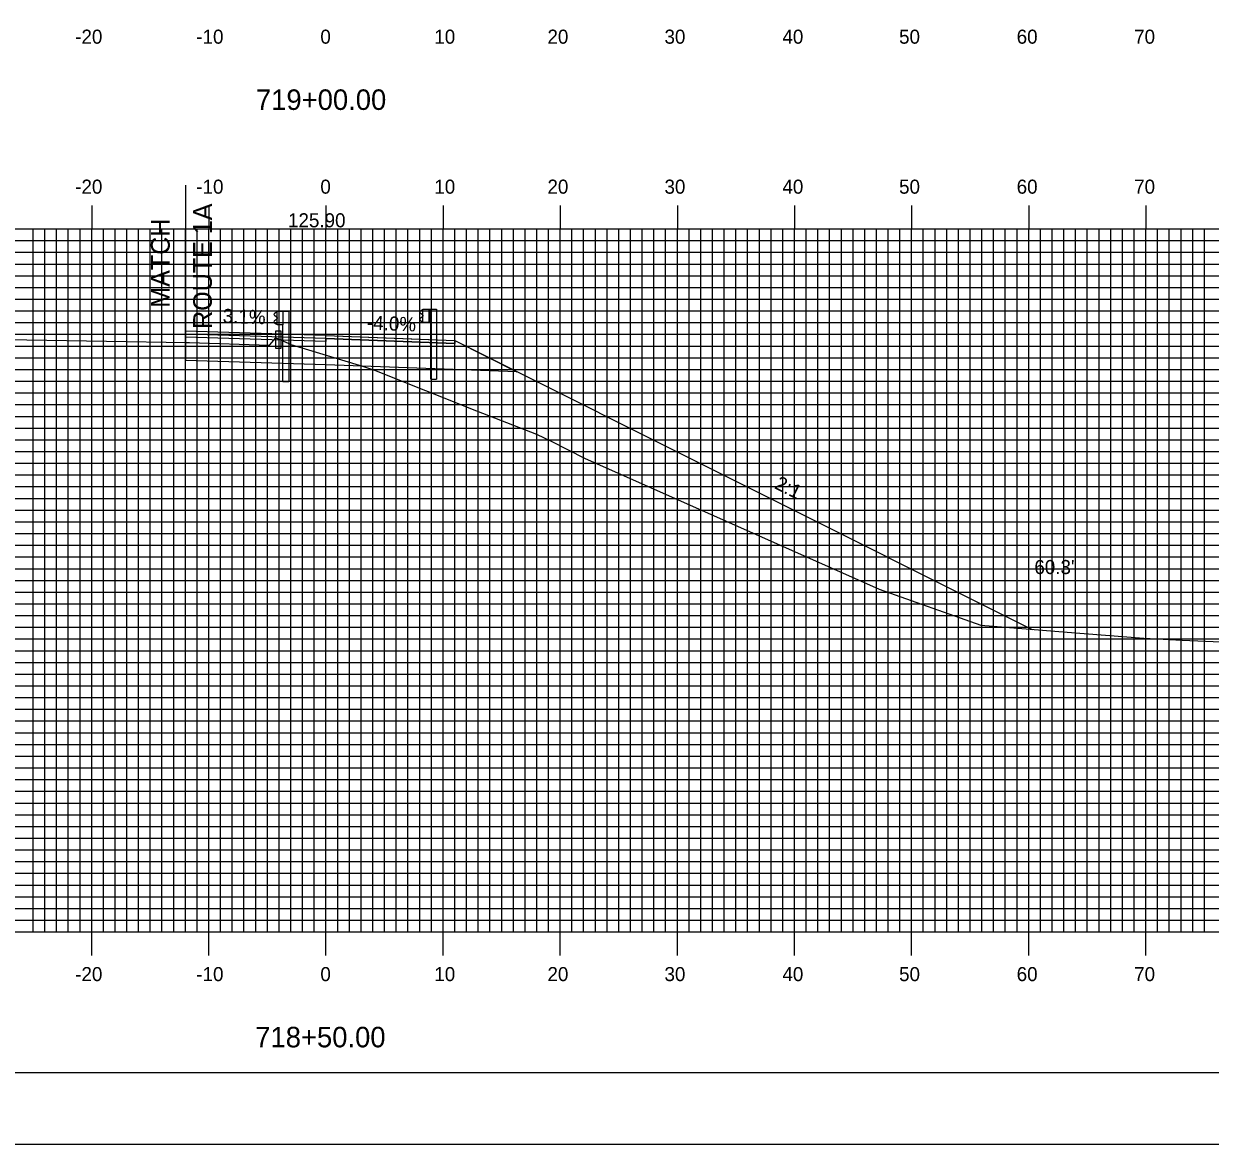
# Model space of a CAD drawing. Extents: x 857658 to 858001, y 364366 to 364586.
# Drawn here: x 857798 to 857899.3, y 364365.7 to 364461.3 of the extents above; entities that cross this region are included whole.
import ezdxf

# ---------------------------------------------------------------- set-up
doc = ezdxf.new("R2010")
doc.units = 0
for name, color, linetype in [('ANNOTATION', 7, 'Continuous'), ('BORDER', 7, 'Continuous'), ('D_Guardrail_Beam_Lt', 7, 'Continuous'), ('D_Roadway_Centerline', 7, 'Continuous'), ('D_Roadway_Centerline_Text', 7, 'Continuous'), ('D_Roadway_Edge_Shoulder', 7, 'Continuous'), ('D_Roadway_Edge_TW', 7, 'Continuous'), ('D_Roadway_Pavement', 7, 'Continuous'), ('D_Roadway_SlopeLines', 7, 'Continuous'), ('D_Roadway_SubGrade', 7, 'Continuous'), ('D_Text_Standard', 7, 'Continuous'), ('H_V ANNOTATION', 7, 'Continuous'), ('MAJOR', 7, 'Continuous'), ('MINOR', 7, 'Continuous'), ('PLOT BOUNDARY', 7, 'Continuous'), ('S_Curb_Type_1', 7, 'Continuous'), ('S_Guardrail_Beam', 7, 'Continuous'), ('S_Roadway_Centerline', 7, 'Continuous')]:
    doc.layers.add(name, color=color, linetype=linetype)

msp = doc.modelspace()

# ---------------------------------------------------------------- linework, layer by layer
at = {"layer": 'BORDER'}
msp.add_lwpolyline([(857674.25, 364371.79), (857994.25, 364371.79), (857994.25, 364581.79), (857674.25, 364581.79)], close=True, dxfattribs=at)
at = {"layer": 'D_Guardrail_Beam_Lt'}
for p, q in [((857832.03, 364436.85), (857831.89, 364436.75)), ((857831.89, 364436.61), (857832.08, 364436.47)), ((857832.08, 364436.27), (857831.89, 364436.14)), ((857832.12, 364436.87), (857832.05, 364436.86)), ((857832.11, 364436.41), (857832.11, 364436.34)), ((857832.12, 364436.95), (857832.81, 364436.95)), ((857832.12, 364435.79), (857832.12, 364436.95)), ((857832.64, 364436.95), (857832.64, 364435.79)), ((857832.74, 364436.95), (857832.74, 364435.79)), ((857832.81, 364436.95), (857833.28, 364436.95)), ((857832.81, 364436.95), (857832.81, 364435.79)), ((857833.28, 364436.95), (857833.28, 364430.95)), ((857831.89, 364435.99), (857832.03, 364435.89)), ((857832.05, 364435.89), (857832.12, 364435.87)), ((857832.81, 364435.79), (857832.12, 364435.79)), ((857832.79, 364430.95), (857832.79, 364435.79)), ((857832.79, 364430.95), (857833.28, 364430.95))]:
    msp.add_line(p, q, dxfattribs=at)
for centre, major_axis, start_param, end_param in [((857831.94, 364436.68), (-0.0877, 0), 5.323254, 7.243116), ((857832.05, 364436.82), (-0.0417, 0), 4.907132, 5.323254), ((857832.04, 364436.41), (0.0789, 0), 0, 0.959931), ((857832.04, 364436.34), (0.0789, 0), 5.323254, 6.283185), ((857831.94, 364436.06), (-0.0877, 0), 5.323254, 7.243116), ((857832.05, 364435.93), (-0.0417, 0), 0.959931, 1.376053)]:
    msp.add_ellipse(centre, major_axis=major_axis, ratio=0.995501, start_param=start_param, end_param=end_param, dxfattribs=at)
at = {"layer": 'D_Roadway_Centerline'}
for p, q in [((857823.85, 364434.69), (857811.85, 364435.06)), ((857823.85, 364434.44), (857811.85, 364434.81)), ((857823.85, 364434.19), (857811.85, 364434.56)), ((857823.85, 364432.19), (857811.85, 364432.56))]:
    msp.add_line(p, q, dxfattribs=at)
at = {"layer": 'D_Roadway_Edge_Shoulder'}
for points in [[(857823.85, 364434.69), (857834.85, 364434.25), (857834.85, 364434), (857823.85, 364434.44)], [(857823.85, 364434.69), (857831.85, 364434.37), (857831.85, 364434.37), (857834.85, 364434.25), (857834.85, 364434), (857823.85, 364434.44)]]:
    msp.add_lwpolyline(points, close=True, dxfattribs=at)
at = {"layer": 'D_Roadway_Edge_TW'}
msp.add_line((857811.85, 364435.12), (857811.85, 364434.87), dxfattribs=at)
at = {"layer": 'D_Roadway_Pavement'}
msp.add_line((857811.85, 364434.87), (857811.85, 364434.62), dxfattribs=at)
msp.add_lwpolyline([(857823.85, 364434.44), (857823.85, 364434.19)], dxfattribs=at)
msp.add_lwpolyline([(857823.85, 364434.44), (857823.85, 364434.19)], dxfattribs=at)
msp.add_lwpolyline([(857823.85, 364434.44), (857823.85, 364434.19)], dxfattribs=at)
msp.add_lwpolyline([(857823.85, 364434.44), (857823.85, 364434.19)], dxfattribs=at)
at = {"layer": 'D_Roadway_SlopeLines'}
msp.add_lwpolyline([(857834.85, 364434.25), (857884.13, 364409.61)], dxfattribs=at)
at = {"layer": 'D_Roadway_SubGrade'}
for p, q in [((857811.85, 364447.52), (857811.85, 364432.56)), ((857811.85, 364434.62), (857811.85, 364432.62))]:
    msp.add_line(p, q, dxfattribs=at)
msp.add_lwpolyline([(857823.85, 364434.19), (857823.85, 364434.44), (857834.85, 364434), (857834.85, 364434.25), (857840.14, 364431.6), (857823.85, 364432.19)], close=True, dxfattribs=at)
at = {"layer": 'MAJOR'}
for p, q in [((857803.85, 364445.79), (857803.85, 364443.79)), ((857813.85, 364445.79), (857813.85, 364443.79)), ((857823.85, 364445.79), (857823.85, 364443.79)), ((857833.85, 364445.79), (857833.85, 364443.79)), ((857843.85, 364445.79), (857843.85, 364443.79)), ((857853.85, 364445.79), (857853.85, 364443.79)), ((857863.85, 364445.79), (857863.85, 364443.79)), ((857873.85, 364445.79), (857873.85, 364443.79)), ((857883.85, 364445.79), (857883.85, 364443.79)), ((857893.85, 364445.79), (857893.85, 364443.79)), ((857683.85, 364443.79), (857963.85, 364443.79)), ((857683.85, 364443.79), (857963.85, 364443.79)), ((857803.85, 364383.79), (857803.85, 364443.79)), ((857813.85, 364383.79), (857813.85, 364443.79)), ((857823.85, 364383.79), (857823.85, 364443.79)), ((857833.85, 364383.79), (857833.85, 364443.79)), ((857843.85, 364383.79), (857843.85, 364443.79)), ((857853.85, 364383.79), (857853.85, 364443.79)), ((857863.85, 364383.79), (857863.85, 364443.79)), ((857873.85, 364383.79), (857873.85, 364443.79)), ((857883.85, 364383.79), (857883.85, 364443.79)), ((857893.85, 364383.79), (857893.85, 364443.79)), ((857683.85, 364438.79), (857963.85, 364438.79)), ((857683.85, 364433.79), (857963.85, 364433.79)), ((857683.85, 364428.79), (857963.85, 364428.79)), ((857683.85, 364423.79), (857963.85, 364423.79)), ((857683.85, 364418.79), (857963.85, 364418.79)), ((857683.85, 364413.79), (857963.85, 364413.79)), ((857683.85, 364408.79), (857963.85, 364408.79)), ((857683.85, 364403.79), (857963.85, 364403.79)), ((857683.85, 364398.79), (857963.85, 364398.79)), ((857683.85, 364393.79), (857963.85, 364393.79)), ((857683.85, 364388.79), (857963.85, 364388.79)), ((857683.85, 364383.79), (857963.85, 364383.79)), ((857683.85, 364383.79), (857963.85, 364383.79)), ((857803.85, 364381.78), (857803.85, 364383.79)), ((857813.85, 364381.78), (857813.85, 364383.79)), ((857823.85, 364381.78), (857823.85, 364383.79)), ((857833.85, 364381.78), (857833.85, 364383.79)), ((857843.85, 364381.78), (857843.85, 364383.79)), ((857853.85, 364381.78), (857853.85, 364383.79)), ((857863.85, 364381.78), (857863.85, 364383.79)), ((857873.85, 364381.78), (857873.85, 364383.79)), ((857883.85, 364381.78), (857883.85, 364383.79)), ((857893.85, 364381.78), (857893.85, 364383.79))]:
    msp.add_line(p, q, dxfattribs=at)
at = {"layer": 'MINOR'}
for p, q in [((857798.85, 364383.79), (857798.85, 364443.79)), ((857799.85, 364383.79), (857799.85, 364443.79)), ((857800.85, 364383.79), (857800.85, 364443.79)), ((857801.85, 364383.79), (857801.85, 364443.79)), ((857802.85, 364383.79), (857802.85, 364443.79)), ((857804.85, 364383.79), (857804.85, 364443.79)), ((857805.85, 364383.79), (857805.85, 364443.79)), ((857806.85, 364383.79), (857806.85, 364443.79)), ((857807.85, 364383.79), (857807.85, 364443.79)), ((857808.85, 364383.79), (857808.85, 364443.79)), ((857809.85, 364383.79), (857809.85, 364443.79)), ((857810.85, 364383.79), (857810.85, 364443.79)), ((857811.85, 364383.79), (857811.85, 364443.79)), ((857812.85, 364383.79), (857812.85, 364443.79)), ((857814.85, 364383.79), (857814.85, 364443.79)), ((857815.85, 364383.79), (857815.85, 364443.79)), ((857816.85, 364383.79), (857816.85, 364443.79)), ((857817.85, 364383.79), (857817.85, 364443.79)), ((857818.85, 364383.79), (857818.85, 364443.79)), ((857819.85, 364383.79), (857819.85, 364443.79)), ((857820.85, 364383.79), (857820.85, 364443.79)), ((857821.85, 364383.79), (857821.85, 364443.79)), ((857822.85, 364383.79), (857822.85, 364443.79)), ((857824.85, 364383.79), (857824.85, 364443.79)), ((857825.85, 364383.79), (857825.85, 364443.79)), ((857826.85, 364383.79), (857826.85, 364443.79)), ((857827.85, 364383.79), (857827.85, 364443.79)), ((857828.85, 364383.79), (857828.85, 364443.79)), ((857829.85, 364383.79), (857829.85, 364443.79)), ((857830.85, 364383.79), (857830.85, 364443.79)), ((857831.85, 364383.79), (857831.85, 364443.79)), ((857832.85, 364383.79), (857832.85, 364443.79)), ((857834.85, 364383.79), (857834.85, 364443.79)), ((857835.85, 364383.79), (857835.85, 364443.79)), ((857836.85, 364383.79), (857836.85, 364443.79)), ((857837.85, 364383.79), (857837.85, 364443.79)), ((857838.85, 364383.79), (857838.85, 364443.79)), ((857839.85, 364383.79), (857839.85, 364443.79)), ((857840.85, 364383.79), (857840.85, 364443.79)), ((857841.85, 364383.79), (857841.85, 364443.79)), ((857842.85, 364383.79), (857842.85, 364443.79)), ((857844.85, 364383.79), (857844.85, 364443.79)), ((857845.85, 364383.79), (857845.85, 364443.79)), ((857846.85, 364383.79), (857846.85, 364443.79)), ((857847.85, 364383.79), (857847.85, 364443.79)), ((857848.85, 364383.79), (857848.85, 364443.79)), ((857849.85, 364383.79), (857849.85, 364443.79)), ((857850.85, 364383.79), (857850.85, 364443.79)), ((857851.85, 364383.79), (857851.85, 364443.79)), ((857852.85, 364383.79), (857852.85, 364443.79)), ((857854.85, 364383.79), (857854.85, 364443.79)), ((857855.85, 364383.79), (857855.85, 364443.79)), ((857856.85, 364383.79), (857856.85, 364443.79)), ((857857.85, 364383.79), (857857.85, 364443.79)), ((857858.85, 364383.79), (857858.85, 364443.79)), ((857859.85, 364383.79), (857859.85, 364443.79)), ((857860.85, 364383.79), (857860.85, 364443.79)), ((857861.85, 364383.79), (857861.85, 364443.79)), ((857862.85, 364383.79), (857862.85, 364443.79)), ((857864.85, 364383.79), (857864.85, 364443.79)), ((857865.85, 364383.79), (857865.85, 364443.79)), ((857866.85, 364383.79), (857866.85, 364443.79)), ((857867.85, 364383.79), (857867.85, 364443.79)), ((857868.85, 364383.79), (857868.85, 364443.79)), ((857869.85, 364383.79), (857869.85, 364443.79)), ((857870.85, 364383.79), (857870.85, 364443.79)), ((857871.85, 364383.79), (857871.85, 364443.79)), ((857872.85, 364383.79), (857872.85, 364443.79)), ((857874.85, 364383.79), (857874.85, 364443.79)), ((857875.85, 364383.79), (857875.85, 364443.79)), ((857876.85, 364383.79), (857876.85, 364443.79)), ((857877.85, 364383.79), (857877.85, 364443.79)), ((857878.85, 364383.79), (857878.85, 364443.79)), ((857879.85, 364383.79), (857879.85, 364443.79)), ((857880.85, 364383.79), (857880.85, 364443.79)), ((857881.85, 364383.79), (857881.85, 364443.79)), ((857882.85, 364383.79), (857882.85, 364443.79)), ((857884.85, 364383.79), (857884.85, 364443.79)), ((857885.85, 364383.79), (857885.85, 364443.79)), ((857886.85, 364383.79), (857886.85, 364443.79)), ((857887.85, 364383.79), (857887.85, 364443.79)), ((857888.85, 364383.79), (857888.85, 364443.79)), ((857889.85, 364383.79), (857889.85, 364443.79)), ((857890.85, 364383.79), (857890.85, 364443.79)), ((857891.85, 364383.79), (857891.85, 364443.79)), ((857892.85, 364383.79), (857892.85, 364443.79)), ((857894.85, 364383.79), (857894.85, 364443.79)), ((857895.85, 364383.79), (857895.85, 364443.79)), ((857896.85, 364383.79), (857896.85, 364443.79)), ((857897.85, 364383.79), (857897.85, 364443.79)), ((857898.85, 364383.79), (857898.85, 364443.79)), ((857683.85, 364442.79), (857963.85, 364442.79)), ((857683.85, 364441.79), (857963.85, 364441.79)), ((857683.85, 364440.79), (857963.85, 364440.79)), ((857683.85, 364439.79), (857963.85, 364439.79)), ((857683.85, 364437.79), (857963.85, 364437.79)), ((857683.85, 364436.79), (857963.85, 364436.79)), ((857683.85, 364435.79), (857963.85, 364435.79)), ((857683.85, 364434.79), (857963.85, 364434.79)), ((857683.85, 364432.79), (857963.85, 364432.79)), ((857683.85, 364431.79), (857963.85, 364431.79)), ((857683.85, 364430.79), (857963.85, 364430.79)), ((857683.85, 364429.79), (857963.85, 364429.79)), ((857683.85, 364427.79), (857963.85, 364427.79)), ((857683.85, 364426.79), (857963.85, 364426.79)), ((857683.85, 364425.79), (857963.85, 364425.79)), ((857683.85, 364424.79), (857963.85, 364424.79)), ((857683.85, 364422.79), (857963.85, 364422.79)), ((857683.85, 364421.79), (857963.85, 364421.79)), ((857683.85, 364420.79), (857963.85, 364420.79)), ((857683.85, 364419.79), (857963.85, 364419.79)), ((857683.85, 364417.79), (857963.85, 364417.79)), ((857683.85, 364416.79), (857963.85, 364416.79)), ((857683.85, 364415.79), (857963.85, 364415.79)), ((857683.85, 364414.79), (857963.85, 364414.79)), ((857683.85, 364412.79), (857963.85, 364412.79)), ((857683.85, 364411.79), (857963.85, 364411.79)), ((857683.85, 364410.79), (857963.85, 364410.79)), ((857683.85, 364409.79), (857963.85, 364409.79)), ((857683.85, 364407.79), (857963.85, 364407.79)), ((857683.85, 364406.79), (857963.85, 364406.79)), ((857683.85, 364405.79), (857963.85, 364405.79)), ((857683.85, 364404.79), (857963.85, 364404.79)), ((857683.85, 364402.79), (857963.85, 364402.79)), ((857683.85, 364401.79), (857963.85, 364401.79)), ((857683.85, 364400.79), (857963.85, 364400.79)), ((857683.85, 364399.79), (857963.85, 364399.79)), ((857683.85, 364397.79), (857963.85, 364397.79)), ((857683.85, 364396.79), (857963.85, 364396.79)), ((857683.85, 364395.79), (857963.85, 364395.79)), ((857683.85, 364394.79), (857963.85, 364394.79)), ((857683.85, 364392.79), (857963.85, 364392.79)), ((857683.85, 364391.79), (857963.85, 364391.79)), ((857683.85, 364390.79), (857963.85, 364390.79)), ((857683.85, 364389.79), (857963.85, 364389.79)), ((857683.85, 364387.79), (857963.85, 364387.79)), ((857683.85, 364386.79), (857963.85, 364386.79)), ((857683.85, 364385.79), (857963.85, 364385.79)), ((857683.85, 364384.79), (857963.85, 364384.79))]:
    msp.add_line(p, q, dxfattribs=at)
at = {"layer": 'PLOT BOUNDARY'}
msp.add_lwpolyline([(857658.06, 364365.67), (857998.06, 364365.67), (857998.06, 364585.67), (857658.06, 364585.67)], close=True, dxfattribs=at)
at = {"layer": 'S_Curb_Type_1'}
msp.add_lwpolyline([(857819.58, 364435.09), (857820, 364435.09), (857820, 364433.59), (857819.58, 364433.59)], close=True, dxfattribs=at)
msp.add_lwpolyline([(857819.58, 364435.09), (857820, 364435.09), (857820, 364433.59), (857819.58, 364433.59)], close=True, dxfattribs=at)
at = {"layer": 'S_Guardrail_Beam'}
for p, q in [((857819.59, 364436.66), (857819.45, 364436.56)), ((857819.59, 364436.66), (857819.45, 364436.56)), ((857819.45, 364436.42), (857819.64, 364436.28)), ((857819.45, 364436.42), (857819.64, 364436.28)), ((857819.69, 364436.68), (857819.61, 364436.67)), ((857819.69, 364436.68), (857819.61, 364436.67)), ((857819.69, 364436.76), (857820.18, 364436.76)), ((857819.69, 364435.59), (857819.69, 364436.76)), ((857819.69, 364436.76), (857820.18, 364436.76)), ((857819.69, 364435.59), (857819.69, 364436.76)), ((857820.18, 364436.76), (857820.67, 364436.76)), ((857820.18, 364436.76), (857820.18, 364435.59)), ((857820.18, 364436.76), (857820.67, 364436.76)), ((857820.18, 364436.76), (857820.18, 364435.59)), ((857820.67, 364436.76), (857820.67, 364430.76)), ((857820.67, 364436.76), (857820.67, 364430.76)), ((857819.64, 364436.06), (857819.45, 364435.93)), ((857819.64, 364436.06), (857819.45, 364435.93)), ((857819.45, 364435.78), (857819.59, 364435.68)), ((857819.45, 364435.78), (857819.59, 364435.68)), ((857819.61, 364435.68), (857819.69, 364435.66)), ((857819.61, 364435.68), (857819.69, 364435.66)), ((857819.68, 364436.22), (857819.68, 364436.13)), ((857819.68, 364436.22), (857819.68, 364436.13)), ((857820.18, 364435.59), (857819.69, 364435.59)), ((857820.18, 364435.59), (857819.69, 364435.59)), ((857820.18, 364430.76), (857820.18, 364435.59)), ((857820.18, 364430.76), (857820.18, 364435.59)), ((857820.18, 364430.76), (857820.67, 364430.76)), ((857820.18, 364430.76), (857820.67, 364430.76))]:
    msp.add_line(p, q, dxfattribs=at)
for centre, major_axis, start_param, end_param in [((857819.5, 364436.49), (-0.0877, 0), 5.323254, 7.243116), ((857819.5, 364436.49), (-0.0877, 0), 5.323254, 7.243116), ((857819.61, 364436.63), (-0.0417, 0), 4.886922, 5.323254), ((857819.61, 364436.63), (-0.0417, 0), 4.886922, 5.323254), ((857819.6, 364436.22), (0.0789, 0), 0, 0.959931), ((857819.6, 364436.22), (0.0789, 0), 0, 0.959931), ((857819.5, 364435.86), (-0.0877, 0), 5.323254, 7.243116), ((857819.5, 364435.86), (-0.0877, 0), 5.323254, 7.243116), ((857819.61, 364435.72), (-0.0417, 0), 0.959931, 1.396263), ((857819.61, 364435.72), (-0.0417, 0), 0.959931, 1.396263), ((857819.6, 364436.13), (0.0789, 0), 5.323254, 6.283185), ((857819.6, 364436.13), (0.0789, 0), 5.323254, 6.283185)]:
    msp.add_ellipse(centre, major_axis=major_axis, ratio=0.995501, start_param=start_param, end_param=end_param, dxfattribs=at)
at = {"layer": 'S_Roadway_Centerline'}
msp.add_lwpolyline([(857794.32, 364434.37), (857798.32, 364434.32), (857811.9, 364434.09), (857812.15, 364434.08), (857812.19, 364434.08), (857819, 364433.85), (857819.05, 364433.88), (857819.58, 364434.5), (857820.82, 364433.95), (857820.86, 364433.93), (857826.67, 364432.15), (857827.05, 364432.04), (857827.98, 364431.72), (857836.7, 364428.25), (857841.81, 364426.28), (857843.12, 364425.64), (857845.93, 364424.21), (857871.08, 364413.05), (857879.76, 364409.98), (857887.13, 364409.36), (857893.68, 364408.85), (857896.96, 364408.7), (857910.89, 364408.09)], dxfattribs=at)

# ---------------------------------------------------------------- texts
at = {"layer": 'ANNOTATION'}
for s, height, rotation, p in [('ROUTE 1A', 1.6, 90, (857814.11, 364435.25)), ('MATCH', 1.6, 90, (857810.51, 364437.06)), ('3.1%', 1.2, 357.94, (857815.02, 364435.77)), ('-4.0%', 1.2, 357.7094, (857827.33, 364435.2)), ('2:1', 1.2, 333.4349, (857862.07, 364421.68))]:
    msp.add_text(s, height=height, rotation=rotation, dxfattribs=at).set_placement(p)
at = {"layer": 'D_Roadway_Centerline_Text'}
msp.add_text('125.90', height=1.2, dxfattribs=at).set_placement((857820.61, 364443.92))
at = {"layer": 'D_Text_Standard'}
msp.add_text("60.3'", height=1.2, dxfattribs=at).set_placement((857884.33, 364414.33))
at = {"layer": 'H_V ANNOTATION'}
for s, height, p in [('-20', 1.2, (857802.44, 364459.59)), ('-10', 1.2, (857812.78, 364459.59)), ('0', 1.2, (857823.37, 364459.59)), ('10', 1.2, (857833.1, 364459.59)), ('20', 1.2, (857842.76, 364459.59)), ('30', 1.2, (857852.75, 364459.59)), ('40', 1.2, (857862.82, 364459.59)), ('50', 1.2, (857872.78, 364459.59)), ('60', 1.2, (857882.82, 364459.59)), ('70', 1.2, (857892.85, 364459.59)), ('719+00.00', 1.75, (857817.87, 364453.94)), ('-20', 1.2, (857802.44, 364446.79)), ('-10', 1.2, (857812.78, 364446.79)), ('0', 1.2, (857823.37, 364446.79)), ('10', 1.2, (857833.1, 364446.79)), ('20', 1.2, (857842.76, 364446.79)), ('30', 1.2, (857852.75, 364446.79)), ('40', 1.2, (857862.82, 364446.79)), ('50', 1.2, (857872.78, 364446.79)), ('60', 1.2, (857882.82, 364446.79)), ('70', 1.2, (857892.85, 364446.79)), ('-20', 1.2, (857802.44, 364379.59)), ('-10', 1.2, (857812.78, 364379.59)), ('0', 1.2, (857823.37, 364379.59)), ('10', 1.2, (857833.1, 364379.59)), ('20', 1.2, (857842.76, 364379.59)), ('30', 1.2, (857852.75, 364379.59)), ('40', 1.2, (857862.82, 364379.59)), ('50', 1.2, (857872.78, 364379.59)), ('60', 1.2, (857882.82, 364379.59)), ('70', 1.2, (857892.85, 364379.59)), ('718+50.00', 1.75, (857817.81, 364373.94))]:
    msp.add_text(s, height=height, dxfattribs=at).set_placement(p)

doc.saveas('drawing.dxf')
